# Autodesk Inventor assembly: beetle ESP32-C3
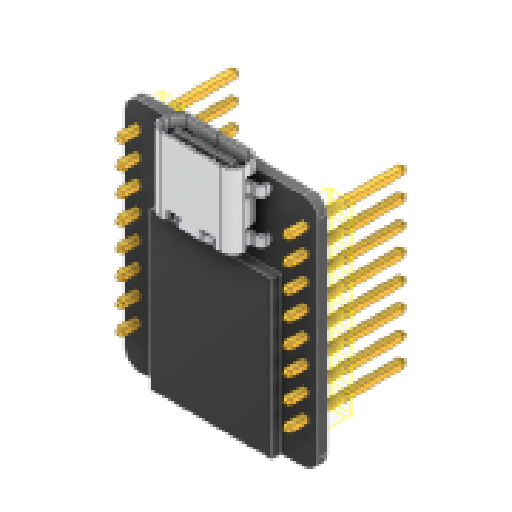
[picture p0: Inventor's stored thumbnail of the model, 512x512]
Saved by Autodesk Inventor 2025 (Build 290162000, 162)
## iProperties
Created: 2022-12
Part Number: beetle ESP32-C3
Document SubType Name: Assembly
Designer: R5800u
Title: beetle ESP32-C3.step
Sending System: Autodesk Translation Framework v11.17.0.187
Preprocessor: ST-DEVELOPER v19.2
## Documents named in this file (4)
- C:\Users\R5800u\Desktop\drone\c3\beetle ESP32-C3\beetle ESP32-C3.iam
- C:\Users\R5800u\Desktop\drone\c3\beetle ESP32-C3\Pin Header 1x8 TH Pitch 2.54mm v2.ipt
- C:\Users\R5800u\Desktop\drone\c3\beetle ESP32-C3\USB TYPE-C-31-M-14 v1.iam
- C:\Users\R5800u\Desktop\drone\c3\beetle ESP32-C3\Parte257.ipt
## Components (4 placed, 3 different names)
1. Pin Header 1x8 TH Pitch 2.54mm v2:1
2. Pin Header 1x8 TH Pitch 2.54mm v2:2
3. USB TYPE-C-31-M-14 v1:1 [sub-assembly]
4. Parte257
